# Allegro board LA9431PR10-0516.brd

Outline 284.1 x 113 mm; copper layers: TOP, GND1, IN1, GND2, IN2, IN3, VCC, IN4, GND3, BOTTOM. Coordinates in mm from the lower left corner of the outline.

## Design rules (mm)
net group _MSE: nets CLK_MSE DAT_MSE
net group BC_CLK_ECE1117: nets BC_CLK_ECE1117 BC_DAT_ECE1117
net group BC_CLK_ECE5048: nets BC_CLK_ECE5048 BC_DAT_ECE5048
net group CHARGER_SMBCLK: nets CHARGER_SMBCLK CHARGER_SMBDAT
net group CLK_DDC2_DOCK: nets CLK_DDC2_DOCK DAT_DDC2_DOCK
net group CLK_KBD: nets CLK_KBD DAT_KBD
net group CLK_PCIE_MINI2: nets CLK_PCIE_MINI2 CLK_PCIE_MINI2#
net group CLK_PCIE_MMI: nets CLK_PCIE_MMI CLK_PCIE_MMI#
net group CPU_DPB_AUX: nets CPU_DPB_AUX CPU_DPB_AUX#
net group CPU_DPB_CTRLCLK: nets CPU_DPB_CTRLCLK CPU_DPB_CTRLDAT
net group CPU_DPB_CTRLCLK_R: nets CPU_DPB_CTRLCLK_R CPU_DPB_CTRLDAT_R
net group CPU_DPC_AUX: nets CPU_DPC_AUX CPU_DPC_AUX#
net group CPU_DPC_CTRLCLK: nets CPU_DPC_CTRLCLK CPU_DPC_CTRLDAT
net group CS1: nets CSN1 CSP1
net group CSS_1: nets CSSN_1 CSSP_1
net group DAT_TP_SIO: nets CLK_TP_SIO DAT_TP_SIO
net group DDR_XDP_SMBCLK_R1: nets DDR_XDP_SMBCLK_R1 DDR_XDP_SMBDAT_R1
net group DIFFPAIR0: nets TMDSB_CON_CLK TMDSB_CON_CLK#
net group DOCK_DCIN_IS: nets DOCK_DCIN_IS+ DOCK_DCIN_IS-
net group DPB_DOCK_AUX: nets DPB_DOCK_AUX DPB_DOCK_AUX#
net group DPC_DOCK_AUX: nets DPC_DOCK_AUX DPC_DOCK_AUX#
net group I2C0_SCL: nets I2C0_SCL I2C0_SDA
net group LAN_SMBCLK: nets LAN_SMBCLK LAN_SMBDATA
net group LAN_SMBCLK_R: nets LAN_SMBCLK_R LAN_SMBDATA_R
net group MDP_AUX: nets MDP_AUX MDP_AUX#
net group MDP_AUX_C: nets MDP_AUX#_C MDP_AUX_C
net group MEM_SMBCLK: nets MEM_SMBCLK MEM_SMBDATA
net group NFC_SMBCLK: nets NFC_SMBCLK NFC_SMBDATA
net group PBAT_SMBCLK: nets PBAT_SMBCLK PBAT_SMBDAT
net group PS_USBP0_D: nets PS_USBP0_D+ PS_USBP0_D-
net group SB3: nets USB3TN2_C USB3TP2_C
net group SENSE: nets VCCSENSE VSSSENSE
net group SML0CLK: nets SML0CLK SML0DATA
net group SML1_SMBCLK: nets SML1_SMBCLK SML1_SMBDATA
net group SW_DPB_AUX: nets SW_DPB_AUX SW_DPB_AUX#
net group SW_DPB_AUX_C: nets SW_DPB_AUX#_C SW_DPB_AUX_C
net group SW_DPC_AUX: nets SW_DPC_AUX SW_DPC_AUX#
net group SW_DPC_AUX_C: nets SW_DPC_AUX#_C SW_DPC_AUX_C
net group TMDS_CLK_C: nets TMDS_CLK#_C TMDS_CLK_C
net group USB3RN2_D: nets USB3RN2_D- USB3RP2_D+
net group USB3RP1_D: nets USB3RN1_D- USB3RP1_D+
net group USB3RP3_D: nets USB3RN3_D- USB3RP3_D+
net group USB3TN1_D: nets USB3TN1_D- USB3TP1_D+
net group USB3TN3_D: nets USB3TN3_D- USB3TP3_D+
net group USB3TP2_D: nets USB3TN2_D- USB3TP2_D+
net group USBP1_R_D: nets USBP1_R_D+ USBP1_R_D-
net group USH_SMBCLK: nets USH_SMBCLK USH_SMBDAT
net group 15: nets USB3TN1 USB3TN1_RP_C USB3TP1 USB3TP1_RP_C
net group ASYNCHRONOUS: nets DDR3_DRAMRST# DDR3_DRAMRST#_CPU H_PROCHOT# H_PROCHOT#_R H_VCCST_PWRGD H_VCCST_PWRGD_XDP PROCHOT#_EC XDP_OBS0_R XDP_OBS1_R XDP_OBS2_R XDP_OBS3_R XDP_OBS4_R XDP_OBS5_R XDP_OBS6_R XDP_OBS7_R
net group CLK_SINGAL: nets CLK_PCI_5048 CLK_PCI_DOCK CLK_PCI_LPDEBUG CLK_PCI_MEC CLK_PCI_TPM_TCM PCI_CLK_LPC PCI_CLK_LPC_0 PCI_CLK_LPC_1
net group CONTROL LINK: nets PCH_CL_CLK1 PCH_CL_DATA1 PCH_CL_RST1#
net group CRT: nets BLUE_DOCK GREEN_DOCK HSYNC_DOCK RED_DOCK VSYNC_DOCK
net group DDR_A_CLK: nets M_CLK_DDR0 M_CLK_DDR1 M_CLK_DDR#0 M_CLK_DDR#1
net group DDR_A_CMD: nets DDR_A_BS0 DDR_A_BS1 DDR_A_BS2 DDR_A_CAS# DDR_A_MA0 DDR_A_MA1 DDR_A_MA2 DDR_A_MA3 DDR_A_MA4 DDR_A_MA5 DDR_A_MA6 DDR_A_MA7 DDR_A_MA8 DDR_A_MA9 DDR_A_MA10 DDR_A_MA11 DDR_A_MA12 DDR_A_MA13 DDR_A_MA14 DDR_A_MA15 DDR_A_RAS# DDR_A_WE#
net group DDR_A_CTL: nets DDR_CKE0_DIMMA DDR_CKE1_DIMMA DDR_CS0_DIMMA# DDR_CS1_DIMMA# M_ODT0 M_ODT1
net group DDR_A_D0: nets DDR_A_D0 DDR_A_D1 DDR_A_D2 DDR_A_D3 DDR_A_D4 DDR_A_D5 DDR_A_D6 DDR_A_D7
net group DDR_A_D1: nets DDR_A_D8 DDR_A_D9 DDR_A_D10 DDR_A_D11 DDR_A_D12 DDR_A_D13 DDR_A_D14 DDR_A_D15
net group DDR_A_D2: nets DDR_A_D16 DDR_A_D17 DDR_A_D18 DDR_A_D19 DDR_A_D20 DDR_A_D21 DDR_A_D22 DDR_A_D23
net group DDR_A_D3: nets DDR_A_D24 DDR_A_D25 DDR_A_D26 DDR_A_D27 DDR_A_D28 DDR_A_D29 DDR_A_D30 DDR_A_D31
net group DDR_A_D4: nets DDR_A_D32 DDR_A_D33 DDR_A_D34 DDR_A_D35 DDR_A_D36 DDR_A_D37 DDR_A_D38 DDR_A_D39
net group DDR_A_D5: nets DDR_A_D40 DDR_A_D41 DDR_A_D42 DDR_A_D43 DDR_A_D44 DDR_A_D45 DDR_A_D46 DDR_A_D47
net group DDR_A_D6: nets DDR_A_D48 DDR_A_D49 DDR_A_D50 DDR_A_D51 DDR_A_D52 DDR_A_D53 DDR_A_D54 DDR_A_D55
net group DDR_A_D7: nets DDR_A_D56 DDR_A_D57 DDR_A_D58 DDR_A_D59 DDR_A_D60 DDR_A_D61 DDR_A_D62 DDR_A_D63
net group DDR_A_DQS: nets DDR_A_DQS0 DDR_A_DQS1 DDR_A_DQS2 DDR_A_DQS3 DDR_A_DQS4 DDR_A_DQS5 DDR_A_DQS6 DDR_A_DQS7 DDR_A_DQS#0 DDR_A_DQS#1 DDR_A_DQS#2 DDR_A_DQS#3 DDR_A_DQS#4 DDR_A_DQS#5 DDR_A_DQS#6 DDR_A_DQS#7
net group DDR_B_CLK: nets M_CLK_DDR2 M_CLK_DDR3 M_CLK_DDR#2 M_CLK_DDR#3
net group DDR_B_CMD: nets DDR_B_BS0 DDR_B_BS1 DDR_B_BS2 DDR_B_CAS# DDR_B_MA0 DDR_B_MA1 DDR_B_MA2 DDR_B_MA3 DDR_B_MA4 DDR_B_MA5 DDR_B_MA6 DDR_B_MA7 DDR_B_MA8 DDR_B_MA9 DDR_B_MA10 DDR_B_MA11 DDR_B_MA12 DDR_B_MA13 DDR_B_MA14 DDR_B_MA15 DDR_B_RAS# DDR_B_WE#
net group DDR_B_CTL: nets DDR_CKE2_DIMMB DDR_CKE3_DIMMB DDR_CS2_DIMMB# DDR_CS3_DIMMB# M_ODT2 M_ODT3
net group DDR_B_D0: nets DDR_B_D0 DDR_B_D1 DDR_B_D2 DDR_B_D3 DDR_B_D4 DDR_B_D5 DDR_B_D6 DDR_B_D7
net group DDR_B_D1: nets DDR_B_D8 DDR_B_D9 DDR_B_D10 DDR_B_D11 DDR_B_D12 DDR_B_D13 DDR_B_D14 DDR_B_D15
net group DDR_B_D2: nets DDR_B_D16 DDR_B_D17 DDR_B_D18 DDR_B_D19 DDR_B_D20 DDR_B_D21 DDR_B_D22 DDR_B_D23
net group DDR_B_D3: nets DDR_B_D24 DDR_B_D25 DDR_B_D26 DDR_B_D27 DDR_B_D28 DDR_B_D29 DDR_B_D30 DDR_B_D31
net group DDR_B_D4: nets DDR_B_D32 DDR_B_D33 DDR_B_D34 DDR_B_D35 DDR_B_D36 DDR_B_D37 DDR_B_D38 DDR_B_D39
net group DDR_B_D5: nets DDR_B_D40 DDR_B_D41 DDR_B_D42 DDR_B_D43 DDR_B_D44 DDR_B_D45 DDR_B_D46 DDR_B_D47
net group DDR_B_D6: nets DDR_B_D48 DDR_B_D49 DDR_B_D50 DDR_B_D51 DDR_B_D52 DDR_B_D53 DDR_B_D54 DDR_B_D55
net group DDR_B_D7: nets DDR_B_D56 DDR_B_D57 DDR_B_D58 DDR_B_D59 DDR_B_D60 DDR_B_D61 DDR_B_D62 DDR_B_D63
net group DDR_B_DQS: nets DDR_B_DQS0 DDR_B_DQS1 DDR_B_DQS2 DDR_B_DQS3 DDR_B_DQS4 DDR_B_DQS5 DDR_B_DQS6 DDR_B_DQS7 DDR_B_DQS#0 DDR_B_DQS#1 DDR_B_DQS#2 DDR_B_DQS#3 DDR_B_DQS#4 DDR_B_DQS#5 DDR_B_DQS#6 DDR_B_DQS#7
net group DP: nets DPB_DOCK_LANE_N0 DPB_DOCK_LANE_N1 DPB_DOCK_LANE_N2 DPB_DOCK_LANE_N3 DPB_DOCK_LANE_P0 DPB_DOCK_LANE_P1 DPB_DOCK_LANE_P2 DPB_DOCK_LANE_P3 DPB_LANE_N0 DPB_LANE_N0_C DPB_LANE_N1 DPB_LANE_N1_C DPB_LANE_N2 DPB_LANE_N2_C DPB_LANE_N3 DPB_LANE_N3_C DPB_LANE_P0 DPB_LANE_P0_C DPB_LANE_P1 DPB_LANE_P1_C DPB_LANE_P2 DPB_LANE_P2_C DPB_LANE_P3 DPB_LANE_P3_C DPC_DOCK_LANE_N0 DPC_DOCK_LANE_N1 DPC_DOCK_LANE_N2 DPC_DOCK_LANE_N3 DPC_DOCK_LANE_P0 DPC_DOCK_LANE_P1 DPC_DOCK_LANE_P2 DPC_DOCK_LANE_P3 DPC_LANE_N0 DPC_LANE_N0_C DPC_LANE_N1 DPC_LANE_N1_C DPC_LANE_N2 DPC_LANE_N2_C DPC_LANE_N3 DPC_LANE_N3_C DPC_LANE_P0 DPC_LANE_P0_C DPC_LANE_P1 DPC_LANE_P1_C DPC_LANE_P2 DPC_LANE_P2_C DPC_LANE_P3 DPC_LANE_P3_C MDP_LANE_N0 MDP_LANE_N0_C MDP_LANE_N1 MDP_LANE_N1_C MDP_LANE_N2 MDP_LANE_N2_C MDP_LANE_N3 MDP_LANE_N3_C MDP_LANE_P0 MDP_LANE_P0_C MDP_LANE_P1 MDP_LANE_P1_C MDP_LANE_P2 MDP_LANE_P2_C MDP_LANE_P3 MDP_LANE_P3_C
net group DP12412_AUX_C: nets DP12412_AUX#_C
net group DP_AUX: nets VMM2310_AUXN VMM2310_AUXP VMM2310_HDP VMM2310_SCL VMM2310_SDA VMM2310_TX2N0 VMM2310_TX2N1 VMM2310_TX2N2 VMM2310_TX2N3 VMM2310_TX2P0
net group DP_DDC: nets VMM_DPB_CTRLCLK VMM_DPB_CTRLDAT VMM_DPC_CTRLCLK VMM_DPC_CTRLDAT
net group DP_MAIN: nets DDI2_LANE_N0 DDI2_LANE_N1 DDI2_LANE_N2 DDI2_LANE_N3 DDI2_LANE_P0 DDI2_LANE_P1 DDI2_LANE_P2 DDI2_LANE_P3 DP12412_AUX DP12412_AUX# DP12412_AUX_C DP12412_N0 DP12412_N0_C DP12412_N1 DP12412_N1_C DP12412_N2 DP12412_N2_C DP12412_N3 DP12412_N3_C DP12412_P0 DP12412_P0_C DP12412_P1 DP12412_P1_C DP12412_P2 DP12412_P2_C DP12412_P3 DP12412_P3_C
net group EDP: nets EDP_CPU_AUX EDP_CPU_AUX# EDP_CPU_AUX#_C EDP_CPU_AUX_C EDP_CPU_LANE_N0 EDP_CPU_LANE_N0_C EDP_CPU_LANE_N1 EDP_CPU_LANE_N1_C EDP_CPU_LANE_P0 EDP_CPU_LANE_P0_C EDP_CPU_LANE_P1 EDP_CPU_LANE_P1_C
net group HDA: nets PCH_AZ_BITCLK PCH_AZ_CODEC_BITCLK PCH_AZ_CODEC_RST# PCH_AZ_CODEC_SDIN0 PCH_AZ_CODEC_SDOUT PCH_AZ_CODEC_SYNC PCH_AZ_RST# PCH_AZ_SDIN0_R PCH_AZ_SDOUT PCH_AZ_SYNC
net group HDMI: nets DDI1_LANE_N0 DDI1_LANE_N1 DDI1_LANE_N2 DDI1_LANE_N3 DDI1_LANE_P0 DDI1_LANE_P1 DDI1_LANE_P2 DDI1_LANE_P3 TMDS_N0_C TMDS_N1_C TMDS_N2_C TMDS_P0_C TMDS_P1_C TMDS_P2_C TMDSB_CON_N0 TMDSB_CON_N1 TMDSB_CON_N2 TMDSB_CON_P0 TMDSB_CON_P1 TMDSB_CON_P2
net group HP: nets AUD_HP_OUT_L AUD_HP_OUT_R AUD_OUT_L AUD_OUT_R
net group LAN: nets DOCK_LOM_TRD0+ DOCK_LOM_TRD0- DOCK_LOM_TRD1+ DOCK_LOM_TRD1- DOCK_LOM_TRD2+ DOCK_LOM_TRD2- DOCK_LOM_TRD3+ DOCK_LOM_TRD3- LAN_TX0+ LAN_TX0+R LAN_TX0- LAN_TX0-R LAN_TX1+ LAN_TX1+R LAN_TX1- LAN_TX1-R LAN_TX2+ LAN_TX2+R LAN_TX2- LAN_TX2-R LAN_TX3+ LAN_TX3+R LAN_TX3- LAN_TX3-R NB_LAN_TX0+ NB_LAN_TX0- NB_LAN_TX1+ NB_LAN_TX1- NB_LAN_TX2+ NB_LAN_TX2- NB_LAN_TX3+ NB_LAN_TX3- SW_LAN_TX0+ SW_LAN_TX0- SW_LAN_TX1+ SW_LAN_TX1- SW_LAN_TX2+ SW_LAN_TX2- SW_LAN_TX3+ SW_LAN_TX3-
net group LOW: nets CFD_PWRBTN#_XDP DSWODVREN H_THERMTRIP# H_THERMTRIP#_R INTRUDER# PCH_DPWROK PCH_INTVRMEN PCH_PCIE_WAKE# PCH_RSMRST#_Q PCH_RSMRST#_R PCH_RTCRST# PM_APWROK SIO_PWRBTN# SIO_RCIN# SRTCRST# SYS_PWROK SYS_PWROK_R SYS_PWROK_XDP SYS_RESET#
net group LPC: nets LPC_LAD0 LPC_LAD1 LPC_LAD2 LPC_LAD3 LPC_LFRAME#
net group MPD: nets SW_MDP_AUX#_C
net group PCIE: nets PCIE_PRX_GLANTX_N3 PCIE_PRX_GLANTX_N3_C PCIE_PRX_GLANTX_P3 PCIE_PRX_GLANTX_P3_C PCIE_PRX_MMITX_N5 PCIE_PRX_MMITX_N5_C PCIE_PRX_MMITX_P5 PCIE_PRX_MMITX_P5_C PCIE_PRX_WLANTX_N4 PCIE_PRX_WLANTX_P4 PCIE_PTX_GLANRX_N3 PCIE_PTX_GLANRX_N3_C PCIE_PTX_GLANRX_P3 PCIE_PTX_GLANRX_P3_C PCIE_PTX_MMIRX_N5 PCIE_PTX_MMIRX_N5_C PCIE_PTX_MMIRX_P5 PCIE_PTX_MMIRX_P5_C PCIE_PTX_WLANRX_N4 PCIE_PTX_WLANRX_N4_C PCIE_PTX_WLANRX_P4 PCIE_PTX_WLANRX_P4_C
net group PLAT_CLK: nets CLK_PCIE_LAN CLK_PCIE_LAN# CLK_PCIE_MINI1 CLK_PCIE_MINI1#
net group POWER: nets +LCDVDD +VCCIO_OUT +VCCIOA_OUT
net group REM: nets REM_DIODE1_N REM_DIODE1_P REM_DIODE2_N REM_DIODE2_P REM_DIODE4_N REM_DIODE4_P
net group RTC: nets PCH_RTCX1 PCH_RTCX1_R PCH_RTCX2
net group SATA: nets SATA_PRX_DKTX_N0 SATA_PRX_DKTX_N0_C SATA_PRX_DKTX_P0 SATA_PRX_DKTX_P0_C SATA_PRX_DTX_N1 SATA_PRX_DTX_N1_C SATA_PRX_DTX_P1 SATA_PRX_DTX_P1_C SATA_PRX_MSATATX_N3 SATA_PRX_MSATATX_P3 SATA_PTX_DKRX_N0 SATA_PTX_DKRX_N0_C SATA_PTX_DKRX_P0 SATA_PTX_DKRX_P0_C SATA_PTX_DRX_N1 SATA_PTX_DRX_N1_C SATA_PTX_DRX_P1 SATA_PTX_DRX_P1_C SATA_PTX_MSATARX_N3 SATA_PTX_MSATARX_N3_C SATA_PTX_MSATARX_P3 SATA_PTX_MSATARX_P3_C
net group SD: nets SD/MMCCD# SD/MMCCLK SD/MMCCLK_R SD/MMCCMD SD/MMCDAT0 SD/MMCDAT0_D SD/MMCDAT1 SD/MMCDAT1_D SD/MMCDAT2 SD/MMCDAT2_R SD/MMCDAT3 SD/MMCDAT3_R SD_UHS2_D0N SD_UHS2_D0N_D SD_UHS2_D0P SD_UHS2_D0P_D SD_UHS2_D1N SD_UHS2_D1N_D SD_UHS2_D1P SD_UHS2_D1P_D SDWP
net group SIM: nets UIM_CLK UIM_DATA UIM_RESET UIM_VPP
net group SMB: nets BAY_SMBCLK BAY_SMBDAT BC_INT#_ECE1117 BC_INT#_ECE5048 CARD_SMBCLK CARD_SMBDAT DDR_XDP_WAN_SMBCLK DDR_XDP_WAN_SMBDAT DOCK_SMB_CLK DOCK_SMB_DAT GPU_SMBCLK GPU_SMBDAT LCD_SMBCLK LCD_SMBDAT WWAN_SMBCLK WWAN_SMBDAT
net group SPI: nets PCH_SPI_CLK PCH_SPI_CS0# PCH_SPI_CS1# PCH_SPI_DIN PCH_SPI_DO PCH_SPI_DO2 PCH_SPI_DO3 SPI_CLK32 SPI_CLK64 SPI_DIN32 SPI_DIN64 SPI_DO32 SPI_DO64 SPI_PCH_CS0#_R SPI_PCH_CS1#_R SPI_PCH_DO2_32 SPI_PCH_DO2_64 SPI_PCH_DO3_32 SPI_PCH_DO3_64
net group SPK: nets INT_SPK_L+ INT_SPK_L- INT_SPK_R+ INT_SPK_R- INT_SPKR_L- INT_SPKR_R+ INT_SPKR_R-
net group SVID: nets H_CPU_SVIDALRT# VIDALERT_N VIDSCLK VIDSOUT
net group SW_MDP_AUX_C: nets SW_MDP_AUX_C
net group THERMAL: nets PECI_EC PECI_EC_R THERMATRIP2#
net group USB2: nets DOCK_USBP0+ DOCK_USBP0- DOCK_USBP0_D+ DOCK_USBP0_D- DOCK_USBP5+ DOCK_USBP5- SW_USBP0+ SW_USBP0- SW_USBP5+ SW_USBP5- USBP0+ USBP0- USBP0_D+ USBP0_D- USBP1+ USBP1- USBP2+ USBP2- USBP3+ USBP3- USBP3_D+ USBP3_D- USBP4+ USBP4- USBP5+ USBP5- USBP5_D+ USBP5_D- USBP6+ USBP6- USBP7+ USBP7-
net group USB3: nets DOCK_USB3RN3 DOCK_USB3RP3 DOCK_USB3TN3 DOCK_USB3TP3 SW_USB3RN3 SW_USB3RP3 SW_USB3TN3 SW_USB3TN3_C SW_USB3TP3 SW_USB3TP3_C USB3RN1 USB3RN2 USB3RN3 USB3RP1 USB3RP2 USB3RP3 USB3TN2 USB3TN3 USB3TP2 USB3TP3
nets with their own width: min track width 0.203; nets CLK_27M_IN CLK_27M_IN_R CLK_27M_OUT MEC_XTAL1 MEC_XTAL2 XTAL24_IN XTAL24_IN_R XTAL24_OUT XTALI XTALO XTALO_R
nets with their own width: min track width 0.254; nets N21375241 NB_PSID RING2_L
nets with their own width: min track width 0.305; nets SM_RCOMP0 SM_RCOMP1 SM_RCOMP2
nets with their own width: min track width 0.356; nets +0.675V_DDR_VTT
nets with their own width: min track width 0.381; nets AUD_HP_OUT_L1
nets with their own width: min track width 0.508; nets +0.675V_P +1.05V_M +1.05V_M_JTAG +1.05V_MP +1.05V_RUN +1.5V_THERMAL +1.05V_VCCST +1.35V_MEN_P +3.3V_ALW +3.3V_ALW2 +3.3V_ALWP +3.3V_CAM_Q +3.3V_HDD +3.3V_MSATA_WWAN +3.3V_RTC_LDO +3.3V_RUN +3.3V_RUN_AUDIO +3.3V_RUN_VDDA +3.3V_RUN_VMM +3.3V_VTR +5V_ALW +5V_ALW2 +5V_ALWP +5V_HDMI_DDC +5V_RUN +ALC290_LDO_CAP +ALC3226_CPVEE +ALC3226_VREF +AUX_LDO +BATT_SUM +CAP_LDO +CHGR_DC_IN +COINCELL +DC1_PWR_SRC +DC_IN +DC_IN_SS +DCIN +DCPRRTC +DIMM1_VREF_DQ +DIMM2_VREF_DQ +DOCK_PWR_BAR +DVDD_CORE +LOM_VCT +NBDOCK_DC_IN_SS +PBATT +PBATT_IN_SS +PCH_ASATA3PLL +PCH_AUSB3PLL +PCH_DCPSUS +PCH_DCPSUS1 +PCH_DCPSUS4 +PCH_RTC_VCCSUS3_3 +PCH_VCC1P05 +PCH_VCCACLKPLL +PCH_VCCDSW +PCH_VCCDSW_R +PECI_VREF +PWR_SRC +PWR_SRC_AC +RSVD_VCC3P3_1 +RTC_CELL +RTC_CELL_VBAT +SD_IO_LDO +SDC_IN +SIM_PWR +SM_VREF_CA +SM_VREF_CA_DIMM +SM_VREF_DQ0 +SM_VREF_DQ0_DIMM1 +SM_VREF_DQ1 +SM_VREF_DQ1_DIMM2 +V1.05S_APLLOPI +V1.05SP_B+ +V_DDR_REF +VCC_CORE +VCC_PWR_SRC +VCHGR +VDDA_AVDD1 +VDDA_AVDD2 +VLDOIN_1.35V +VR_CAP +VREFOUT EDP_COMP GND GNDA
nets with their own width: min track width 1.016; nets +0.9V_LAN +1.2V_LDO +1.2V_LDO_AIN +1.05V_VMM_VDD +1.8V_RUN_CARD +3.3V_ALW_PCH +3.3V_ALW_U37 +3.3V_ALW_U38 +3.3V_CAM +3.3V_LAN +3.3V_LAN_OUT +3.3V_M +3.3V_RUN_AIN +3.3V_RUN_CARD +3.3V_RUN_TPM +3.3V_RUN_VDDIO +3.3V_TP +3.3V_TSP +3.3V_TSP_Q +BL_PWR_SRC +GND_CHASSIS +PCH_VCCDSW3_3 +VDDA_PVDD +VDISPLAY_VCC +VHDMI_VCC REGCTL_PNP10
nets with their own width: min track width 1.524; nets +1.05V_VMM_VDDTX +3.3V_SUS +3.3V_WLAN +USB_SIDE_PWR
nets with their own width: min track width 2.032; nets +1.05V_MODPHY +1.05V_MODPHY_PCH +1.05V_RUN_VMM +5V_RUN_AUDIO +USB_PWR
nets with their own width: min track width 2.54; nets +5V_USB_CHG_PWR

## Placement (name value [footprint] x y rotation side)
C1  -  [C_0402]  248.34 8.6 90 top
C3  -  [C_0402]  94.3 97.38 180 bottom
C5  -  [C_0402]  177.52 83.86 0 bottom
C6  -  [C_0402]  175.43 65.44 0 bottom
C7  -  [C_0805]  50.85 45.15 270 top
C8  -  [C_0603]  197.16 77.95 270 bottom
C9  -  [C_0402]  192.19 83.16 0 bottom
C10  -  [C_0402]  196.99 80.63 270 bottom
C11  -  [C_0402]  196.96 84.06 270 bottom
C12  -  [C_0402]  199.52 81.25 0 bottom
C13  -  [C_0402]  198.27 81.18 90 bottom
C14  -  [C_0402]  197.76 84.96 180 bottom
C15  -  [C_0402]  199.59 80.39 270 bottom
C16  -  [C_0603]  197.73 86.08 180 bottom
C17  -  [C_0402]  195.33 78.59 180 bottom
C18  -  [C_0402]  195.29 77.34 180 bottom
C19  -  [C_0402]  187.16 79.76 0 top
C20  -  [C_0402]  187.16 78.88 0 top
C21  -  [C_0603]  203.81 75.93 0 bottom
C22  -  [C_0402]  195.05 84.75 0 bottom
C23  -  [C_0402]  199.57 82.26 90 bottom
C24  -  [C_0402]  192.33 81.53 270 bottom
C25  -  [C_0603]  192.91 75.09 90 bottom
C26  -  [C_0603]  189.43 89.06 90 top
C27  -  [C_0402]  198.35 78.61 0 bottom
C28  -  [C_0402]  193.27 84.75 0 bottom
C29  -  [C_0402]  198.79 84.68 0 bottom
C34  -  [C_0402]  191.87 77.44 0 bottom
C42  -  [C_0402]  188.07 77.11 90 top
C43  -  [C_0402]  187.95 76.12 270 top
C50  -  [C_0402]  270.04 6.32 0 top
C52  -  [C_0603]  65.52 70.21 180 bottom
C54  -  [C_0402]  60.13 67.89 110 bottom
C55  -  [C_0402]  59.24 67.57 110 bottom
C56  -  [C_0402]  57.25 67.81 110 bottom
C57  -  [C_0402]  57.2 65.19 110 bottom
C59  -  [C_0402]  58.09 68.12 110 bottom
C60  -  [C_0402]  58.03 65.5 110 bottom
C61  -  [C_0402]  146.67 103.78 90 top
C62  -  [C_0402]  140.58 102.7 90 top
C63  -  [C_0402]  59.49 70.83 90 bottom
C64  -  [C_0402]  53.21 67.22 0 top
C65  -  [C_0603]  65.52 71.92 180 bottom
C66  -  [C_0402]  70.61 66.9 180 top
C67  -  [C_0402]  87.99 94.63 180 top
C68  -  [C_0402]  67.22 77.06 0 top
C76  -  [C_0402]  178.88 81 180 bottom
C85  -  [C_0402]  178.3 75.55 270 bottom
C87  -  [C_0402]  199.24 99.85 180 bottom
C88  -  [C_0603]  187.38 98.93 270 bottom
C93  -  [C_0402]  210.55 83.36 270 bottom
C94  -  [C_0402]  201.47 83.17 270 bottom
C95  -  [C_0402]  200.52 83.17 270 bottom
C97  -  [C_0402]  180.33 82.57 90 bottom
C98  -  [C_0402]  185.37 89.9 0 bottom
C99  -  [C_0402]  185.37 88.95 0 bottom
C103  -  [C_0402]  193.85 94.86 270 bottom
C105  -  [C_0402]  45.4 15.85 180 top
C106  -  [C_0402]  45.4 16.74 180 top
C108  -  [C_0402]  45.4 20.09 180 top
C109  -  [C_0402]  45.4 19.2 180 top
C113  -  [C_0402]  50.27 13.21 0 bottom
C114  -  [C_0402]  50.27 12.25 0 bottom
C115  -  [C_0402]  275.72 42.77 180 top
C116  -  [C_0603]  268.31 40.17 90 top
C117  -  [C_0603]  275.2 43.98 180 top
C118  -  [C_0603]  264.91 31.34 90 top
C119  -  [C_0402]  271.41 28.51 270 top
C120  -  [C_0402]  275.04 28.52 270 top
C121  -  [C_0603]  269.44 28.88 270 top
C122  -  [C_0603]  267.67 34.96 180 top
C123  -  [C_0402]  267.2 33.15 180 top
C124  -  [C_0402]  280.39 21.75 180 top
C125  -  [C_0402]  277.66 21.75 0 top
C126  -  [C_0402]  275.91 21.88 180 top
C127  -  [C_0402]  272.9 21.88 0 top
C128  -  [C_0603]  267.55 37.19 180 top
C129  -  [C_0402]  267.61 36.04 180 top
C130  -  [C_0402]  270.52 26.8 270 top
C131  -  [C_0603]  271.77 42.39 0 bottom
C132  -  [C_0603]  200.42 76.97 270 bottom
C134  -  [C_0603]  269.58 39.47 0 top
C135  -  [C_0402]  272.55 26.75 270 top
C136  -  [C_0402]  273.42 26.73 270 top
C137  -  [C_0402]  278 23.41 180 top
C138  -  [C_0603]  270.85 40.74 180 top
C139  -  [C_0402]  269.8 16.42 0 top
C140  -  [C_0603]  275.72 42.76 90 bottom
C141  -  [C_0402]  270.36 66.37 90 top
C142  -  [C_0402]  269.42 66.38 90 top
C144  -  [C_0402]  267.14 42.27 180 top
C145  -  [C_0402]  275.2 24.19 0 top
C146  -  [C_0402]  275.2 25.09 0 top
C147  -  [C_0402]  270.31 19.23 0 top
C148  -  [C_0402]  270.31 18.34 0 top
C150  -  [C_0402]  267.93 39.23 270 top
C151  -  [C_0603]  164.07 83.6 270 top
C152  -  [C_0402]  166.17 83.3 270 top
C153  -  [C_0402]  165.21 83.3 270 top
C154  -  [C_0402]  165.93 89.51 180 top
C155  -  [C_0402]  187.17 80.68 0 top
C156  -  [C_0402]  187.17 81.57 0 top
C157  -  [C_0402]  187.17 82.46 0 top
C158  -  [C_0402]  187.17 83.35 0 top
C159  -  [C_0402]  187.19 84.24 0 top
C160  -  [C_0402]  187.19 85.13 0 top
C161  -  [C_0402]  187.17 86.02 0 top
C162  -  [C_0402]  187.17 86.91 0 top
C163  -  [C_0402]  178.54 87.99 0 top
C164  -  [C_0402]  178.54 87.1 0 top
C165  -  [C_0402]  178.16 86.14 0 top
C166  -  [C_0402]  178.16 85.25 0 top
C167  -  [C_0402]  274.17 43.89 270 bottom
C168  -  [C_0402]  178.52 83.38 270 top
C169  -  [C_0603]  273.22 43.64 180 bottom
C170  -  [C_0402]  177.63 83.38 270 top
C171  -  [C_0402]  271.68 87.74 180 top
C172  -  [C_0402]  176.71 82.6 270 top
C173  -  [C_0402]  175.82 82.6 270 top
C174  -  [C_0402]  227.52 89.16 180 top
C175  -  [C_0402]  227.52 87.21 180 top
C176  -  [C_0402]  250.54 71.97 270 top
C177  -  [C_0402]  253.8 82.51 90 top
C178  -  [C_0402]  252.39 71.05 90 top
C179  -  [C_0402]  249.66 71.97 270 top
C180  -  [C_0603]  256.91 70.71 90 top
C181  -  [C_0402]  253.28 71.05 90 top
C182  -  [C_0603]  258.5 81.76 90 top
C183  -  [C_0402]  251.13 82.45 90 top
C184  -  [C_0402]  255.83 71.28 90 top
C185  -  [C_0402]  251.45 71.93 270 top
C186  -  [C_0402]  248.72 71.93 270 top
C187  -  [C_0805]  258.43 70.75 90 top
C188  -  [C_0402]  268.83 21.13 180 top
C189  -  [C_0402]  259.19 78.03 270 top
C190  -  [C_0402]  259.19 78.89 90 top
C191  -  [C_0402]  194.81 94.86 270 bottom
C192  -  [C_0402]  230.51 97.05 270 top
C193  -  [C_0402]  230.35 99.42 0 bottom
C194  -  [C_0402]  228.7 97.21 180 top
C198  -  [C_0402]  243.03 81.94 0 top
C199  -  [C_0402]  196.33 94.69 270 bottom
C200  -  [C_0402]  40.56 38.32 90 top
C201  -  [C_0402]  41.96 28.69 270 top
C202  -  [C_0402]  41.01 28.69 270 top
C203  -  [C_0402]  37.77 28.69 270 top
C204  -  [C_0402]  38.72 28.69 270 top
C206  -  [C_0402]  186.84 8.09 90 top
C207  -  [C_0402]  187.76 8.09 90 top
C208  -  [C_0402]  188.65 8.09 90 top
C209  -  [C_0402]  197.28 94.69 270 bottom
C210  -  [C_0402]  263.37 19.85 0 top
C211  -  [C_0603]  252.27 26.07 180 top
C212  -  [C_0402]  255.45 25.68 90 top
C213  -  [C_0603]  253.8 12.04 180 top
C214  -  [C_0402]  257.29 25.68 90 top
C215  -  [C_0402]  255.38 14.78 270 top
C216  -  [C_0402]  253.61 14.73 90 top
C217  -  [C_0402]  264.52 18.96 180 top
C218  -  [C_0402]  256.4 26.59 270 top
C219  -  [C_0402]  250.93 17.94 0 top
C220  -  [C_0603]  252.53 13.37 90 top
C221  -  [C_0603]  253.48 26.71 270 top
C222  -  [C_0402]  254.56 26.59 270 top
C223  -  [C_0603]  265.07 17.88 180 top
C224  -  [C_0603]  250.88 24.8 0 top
C225  -  [C_0603]  250.88 23.53 0 top
C226  -  [C_0402]  251.82 22.45 0 top
C227  -  [C_0402]  249.24 20.28 180 top
C228  -  [C_0603]  251.55 15.99 180 top
C229  -  [C_0402]  251.63 17.07 180 top
C230  -  [C_0603]  264.91 26.01 180 top
C231  -  [C_0402]  262.62 25.74 180 top
C232  -  [C_0402]  256.27 13.87 90 top
C233  -  [C_0402]  258.12 13.87 90 top
C234  -  [C_0402]  260.85 14.06 90 top
C235  -  [C_0402]  261.43 28.04 180 top
C236  -  [C_0402]  261.43 27.15 180 top
C237  -  [C_0402]  263.53 28.68 180 top
C238  -  [C_0402]  263.53 29.57 180 top
C239  -  [C_0402]  249.24 18.06 180 top
C240  -  [C_0603]  249.73 19.14 180 top
C241  -  [C_0402]  210.26 14.92 180 top
C242  -  [C_0402]  207.7 22.67 0 bottom
C243  -  [C_0402]  207.7 23.56 0 bottom
C244  -  [C_0402]  205.54 59.41 270 top
C245  -  [C_0402]  204.65 59.41 270 top
C246  -  [C_0402]  274.69 5.12 180 top
C247  -  [C_0603]  274.78 6.2 180 top
C248  -  [C_0402]  206.81 61.96 270 top
C249  -  [C_0402]  207.44 66.45 90 top
C250  -  [C_0402]  205.91 43.93 90 top
C251  -  [C_0805]  206.08 64.32 90 top
C252  -  [C_0402]  206.62 53.45 270 top
C253  -  [C_B2]  204.1 61.67 270 bottom
C254  -  [C_B2]  204.04 58.84 90 bottom
C255  -  [C_0402]  264.29 21.69 180 top
C256  -  [C_0402]  249.21 15.82 180 top
C257  -  [C_0402]  207.2 26.62 270 bottom
C258  -  [C_0402]  208.1 26.62 270 bottom
C259  -  [C_0402]  210.86 9.28 90 top
C260  -  [C_0402]  209 25.7 90 bottom
C261  -  [C_0402]  210.76 21.73 270 top
C262  -  [C_0603]  209.58 20.83 90 top
C269  -  [C_0402]  191.5 94.86 270 bottom
C270  -  [C_0402]  192.39 94.86 270 bottom
C271  -  [C_0402]  189.22 94.86 270 bottom
C272  -  [C_0402]  190.17 94.86 270 bottom
C273  -  [C_0402]  193.6 99.15 90 bottom
C274  -  [C_0402]  195 99.15 90 bottom
C275  -  [C_0402]  196.08 99.15 90 bottom
C276  -  [C_0402]  197.35 99.15 90 bottom
C277  -  [C_0402]  191.19 99.15 90 bottom
C278  -  [C_0402]  192.58 99.15 90 bottom
C279  -  [C_0402]  188.9 99.15 90 bottom
C280  -  [C_B2]  226.01 90.78 180 bottom
C281  -  [C_0402]  219.65 94.72 180 top
C282  -  [C_0402]  203.3 93.33 180 top
C283  -  [C_0402]  203.3 92.44 180 top
C284  -  [C_0603]  231.99 87.25 0 bottom
C285  -  [C_0402]  232.32 85.95 0 bottom
C287  -  [C_0402]  71.49 85.46 270 top
C288  -  [C_0603]  103.49 103.06 270 top
C289  -  [C_0402]  103.05 104.23 90 top
C290  -  [C_B2]  83.01 96.35 0 bottom
C291  -  [C_0402]  76.11 96.3 0 top
C292  -  [C_0402]  78.09 87.43 270 top
C293  -  [C_0402]  79.05 87.43 270 top
C294  -  [C_0402]  114.21 93.34 90 top
C295  -  [C_0402]  115.1 94.26 270 bottom
C296  -  [C_0402]  115.1 93.34 90 top
C297  -  [C_0402]  115.99 94.26 270 bottom
C298  -  [C_0402]  115.99 93.34 90 top
C299  -  [C_0402]  116.88 94.26 270 bottom
C300  -  [C_0402]  119.54 94.26 270 bottom
C301  -  [C_0402]  120.43 94.26 270 bottom
C302  -  [C_0402]  114.21 94.26 270 bottom
C303  -  [C_0402]  116.88 93.34 90 top
C304  -  [C_0402]  117.77 94.26 270 bottom
C305  -  [C_0402]  117.77 93.34 90 top
C306  -  [C_0402]  118.66 94.26 270 bottom
C307  -  [C_0402]  118.66 93.34 90 top
C308  -  [C_0402]  119.54 93.34 90 top
C309  -  [C_0402]  120.43 93.34 90 top
C310  -  [C_0402]  122.72 96.92 270 bottom
C311  -  [C_0402]  123.38 109 180 top
C312  -  [C_0402]  128.7 104.99 90 top
C313  -  [C_0402]  129.65 104.99 90 top
C314  -  [C_0402]  138.15 97.51 0 top
C315  -  [C_0402]  138.15 98.4 0 top
C316  -  [C_0402]  144.26 109.02 270 top
C317  -  [C_0603]  111.8 96.8 270 bottom
C318  -  [C_0603]  108.26 93.07 0 bottom
C319  -  [C_0402]  147.43 96.35 90 bottom
C320  -  [C_0402]  244.08 96.84 270 top
C321  -  [C_0402]  243.19 96.84 270 top
C322  -  [C_0402]  79.67 83.03 0 top
C323  -  [C_0603]  259.64 81.95 270 bottom
C324  -  [C_0603]  258.37 81.95 270 bottom
C325  -  [C_0603]  247.7 81.83 270 bottom
C326  -  [C_0603]  246.37 81.83 270 bottom
C327  -  [C_1808]  267.21 86.11 180 bottom
C328  -  [C_0603]  16 42.52 180 top
C329  -  [C_0402]  19.74 41.74 90 bottom
C330  -  [C_0402]  13.36 32.92 180 top
C331  -  [C_0402]  12.76 35.22 180 top
C332  -  [C_0402]  28.55 30.07 0 top
C333  -  [C_0402]  184.98 100.75 180 bottom
C334  -  [C_0402]  18.34 41.74 90 bottom
C336  -  [C_0603]  18.86 40.22 0 bottom
C337  -  [C_0402]  12.89 39.33 90 top
C338  -  [C_0402]  194.6 41.76 0 top
C339  -  [C_0402]  30.71 36.3 0 top
C340  -  [C_0402]  11.81 6.26 180 top
C341  -  [C_0402]  256.41 29.57 180 top
C342  -  [C_0402]  12.64 3.47 180 top
C343  -  [C_0402]  12.64 7.21 180 top
C344  -  [C_0402]  14.48 4.36 180 top
C345  -  [C_0402]  14.54 14.26 180 top
C346  -  [C_0402]  32.88 13.32 270 top
C347  -  [C_0402]  17.34 14.44 180 top
C348  -  [C_0603]  16.07 5.63 90 top
C349  -  [C_0402]  19.1 7.29 270 top
C350  -  [C_0402]  31.98 15.98 0 top
C351  -  [C_0402]  25.9 7.29 270 top
C352  -  [C_0402]  31.99 13.32 270 top
C353  -  [C_0402]  17.34 13.55 180 top
C354  -  [C_0402]  29.58 22.25 90 top
C355  -  [C_0402]  17.34 17.18 180 top
C356  -  [C_0402]  24.18 22.25 90 top
C357  -  [C_0402]  35.24 11.53 180 top
C358  -  [C_0402]  28.13 7.28 180 top
C359  -  [C_0402]  29.29 6.27 180 top
C360  -  [C_0402]  19.37 22.2 180 top
C361  -  [C_0402]  29.82 7.28 0 top
C362  -  [C_0402]  12 16.55 180 top
C363  -  [C_0402]  34.26 16.85 0 top
C364  -  [C_0402]  15.55 12.09 90 top
C365  -  [C_0402]  15.55 11.16 270 top
C366  -  [C_0603]  27.23 4.93 0 top
C367  -  [C_0402]  31.98 9.69 0 top
C368  -  [C_0402]  24.99 4.8 0 top
C369  -  [C_0402]  24.94 7.29 270 top
C370  -  [C_0402]  128.7 72.38 270 top
C371  -  [C_0402]  31.98 19.04 0 top
C372  -  [C_0402]  126.5 17.47 180 top
C373  -  [C_0402]  93.27 57.01 270 bottom
C374  -  [C_0402]  199.44 8.34 90 top
C375  -  [C_0402]  202.3 8.34 90 top
C376  -  [C_0402]  203.19 8.34 90 top
C377  -  [C_0402]  192.7 16.49 0 top
C378  -  [C_0402]  190.06 16.31 0 top
C379  -  [C_0402]  192.66 14.02 180 top
C380  -  [C_0402]  189.78 13.99 0 top
C382  -  [C_0402]  190.23 99.15 90 bottom
C383  -  [C_0402]  269.37 82.35 0 top
C384  -  [C_0402]  36.82 38.38 90 top
C385  -  [C_0603]  270.84 41.99 180 top
C386  -  [C_0402]  41.33 9.64 270 top
C387  -  [C_0402]  38.04 18.64 180 top
C388  -  [C_0402]  249.89 14.4 180 top
C389  -  [C_0402]  204.72 72.36 270 bottom
C390  -  [C_0402]  208.48 70.51 270 bottom
C391  -  [C_0402]  209.37 70.51 270 bottom
C392  -  [C_0402]  194.17 72.36 90 bottom
C393  -  [C_0402]  212.71 71.11 0 bottom
C394  -  [C_0402]  196.66 73.84 0 top
C396  -  [C_0402]  189.76 31.29 180 top
C397  -  [C_0402]  189.75 32.44 180 top
C398  -  [C_0402]  189.75 33.45 180 top
C399  -  [C_0402]  188.77 35.27 180 top
C400  -  [C_0402]  185.75 68.1 180 top
C401  -  [C_0402]  186.49 68.57 270 bottom
C402  -  [C_0402]  188.9 68.57 270 bottom
C403  -  [C_0402]  189.51 71.21 0 top
C404  -  [C_0402]  10 37.86 90 top
C405  -  [C_0603]  262.62 31.34 90 top
C406  -  [C_0402]  246.32 73.82 180 top
C407  -  [C_0402]  203.94 39 90 top
C408  -  [C_0603]  272.97 47.73 180 bottom
C409  -  [C_0402]  203.91 28.63 90 top
C410  -  [C_0603]  267.81 30.77 180 top
C411  -  [C_0402]  235.27 91.26 180 top
C412  -  [C_0402]  157.73 91.08 270 top
C413  -  [C_0603]  147.92 90.35 0 top
C414  -  [C_0402]  157.42 111.48 180 top
C415  -  [C_0402]  155.64 111.48 180 top
C416  -  [C_0402]  167.51 99.35 180 top
C417  -  [C_0402]  159.59 105.68 90 top
C418  -  [C_0402]  167.83 98.46 180 top
C419  -  [C_0402]  167.51 100.81 180 top
C420  -  [C_0603]  167.63 108.56 90 top
C422  -  [C_0402]  205.35 27.05 90 top
C425  -  [C_0402]  202.08 35.83 0 top
C426  -  [C_0402]  202.3 40.36 180 top
C427  -  [C_0402]  203.95 38.16 270 top
C428  -  [C_0402]  201.9 28.74 90 top
C429  -  [C_0402]  202.96 28.63 90 top
C430  -  [C_0402]  50.65 72.55 0 top
C431  -  [C_0603]  60.76 70.27 90 bottom
C432  -  [C_0402]  198.93 73.43 270 bottom
C433  -  [C_0402]  198.76 75.03 180 bottom
C440  -  [C_0402]  273.43 50.47 270 top
C441  -  [C_0402]  273.41 52.63 270 top
C442  -  [C_0402]  278.99 49.76 0 bottom
C443  -  [C_0402]  275.98 48.92 0 bottom
C444  -  [C_B2]  267.5 82.79 0 bottom
C445  -  [C_0402]  268.5 72.06 90 top
C446  -  [C_0603]  230.43 83.27 180 bottom
C447  -  [C_0402]  230.48 84.3 180 bottom
C448  -  [C_0402]  263.29 85.52 135 top
C449  -  [C_0402]  262.66 84.89 135 top
C451  -  [C_0402]  163.96 88.02 0 top
C452  -  [C_0603]  158.98 18.43 270 top
C453  -  [C_0603]  181.84 73.01 180 top
C454  -  [C_0603]  96.06 56.55 270 top
C455  -  [C_0402]  31.59 7.86 0 top
C456  -  [C_0402]  10.48 21.08 0 top
C457  -  [C_0402]  15.03 6.6 270 top
C458  -  [C_0603]  133.07 76.71 270 top
C459  -  [C_0603]  134.38 76.72 270 top
C460  -  [C_0603]  128.42 70.57 270 top
C461  -  [C_0603]  137.39 67.65 0 top
CC1  -  [C_0402]  155.28 57.43 90 bottom
CC2  -  [C_0402]  155.28 56.57 270 bottom
CC3  -  [C_0402]  57.71 56.44 270 bottom
CC4  -  [C_0402]  56.81 60.2 270 bottom
CC5  -  [C_0402]  157.14 50.46 0 top
CC6  -  [C_0402]  137.9 88.87 0 bottom
CC7  -  [C_0402]  136.12 87.92 0 bottom
CC8  -  [C_0402]  168.14 74.7 90 top
CC9  -  [C_0402]  170.23 58.08 180 top
CC10  -  [C_0402]  58.61 60.17 180 top
CC11  -  [C_0402]  69.63 59.66 0 top
CC12  -  [C_0402]  124.59 56.87 180 top
CC13  -  [C_0402]  129.01 56.74 0 top
CC14  -  [C_0402]  147.83 52.04 180 top
CC15  -  [C_0402]  140.83 56.82 270 top
CC16  -  [C_0603]  128.77 55.66 0 top
CC17  -  [C_0603]  122.87 54.94 180 top
CC18  -  [C_0603]  128.77 54.39 0 top
CC19  -  [C_0603]  126.86 56.04 180 top
CC20  -  [C_0603]  126.86 54.77 180 top
CC21  -  [C_0603]  122.35 56.17 180 top
CC22  -  [C_0402]  109.98 93.65 270 top
CC24  -  [C_0402]  111.81 96.86 90 top
CC26  -  [C_0402]  136.65 69.62 180 top
CC27  -  [C_0402]  148.67 87.71 0 top
CC28  -  [C_0603]  141.47 69.82 90 top
CC29  -  [C_0402]  148.67 86.82 0 top
CC30  -  [C_0402]  165.03 61.61 270 bottom
CC31  -  [C_0402]  138.35 74.26 90 top
CC32  -  [C_0402]  145.8 68.43 180 top
CC33  -  [C_0402]  141.02 67.53 90 top
CC34  -  [C_0603]  137.2 90.14 0 top
CC35  -  [C_0402]  143.69 67.65 90 top
CC36  -  [C_0402]  154.69 68.99 0 top
CC37  -  [C_0402]  138.51 68.71 90 top
CC38  -  [C_0402]  142.77 68.43 180 top
CC39  -  [C_0402]  143.76 66.29 180 top
CC40  -  [C_0402]  144.78 73.13 180 top
CC41  -  [C_0402]  74.47 74.55 270 top
CC42  -  [C_0603]  140.77 87.53 90 bottom
CC43  -  [C_0603]  142.61 72.62 180 top
CC44  -  [C_0402]  139.88 69.43 90 top
CC45  -  [C_0402]  141.15 74.6 270 top
CC46  -  [C_0402]  142.55 69.87 90 top
CC47  -  [C_0805]  156.73 94.14 180 bottom
CC48  -  [C_0402]  69.63 62.33 0 top
CC49  -  [C_0603]  144.26 90.41 180 top
CC50  -  [C_0603]  135.14 90.13 180 top
CC51  -  [C_0402]  141.86 77 180 top
CC52  -  [C_0402]  129.46 67.65 90 top
CC53  -  [C_0402]  144.78 72.17 180 top
CC54  -  [C_0402]  144.34 70.84 180 top
CC55  -  [C_1206]  151.73 89.76 0 bottom
CC56  -  [C_0402]  139.88 72.12 270 top
CC58  -  [C_0402]  139.66 87.91 90 bottom
CC59  -  [C_0402]  141.16 75.48 180 top
CC60  -  [C_0402]  145.78 75.74 270 top
CC61  -  [C_0402]  142.61 87.97 90 top
CC62  -  [C_0603]  139.24 91.29 90 top
CC63  -  [C_0402]  142.57 74.98 270 top
CC64  -  [C_0402]  143.46 74.98 270 top
CC65  -  [C_0402]  139.37 55.04 270 top
CC66  -  [C_0402]  143.61 77.18 180 top
CC67  -  [C_0402]  114.05 16.48 180 top
CC68  -  [C_0402]  58.61 61.94 180 top
CC69  -  [C_0402]  135.82 29.35 270 top
CC70  -  [C_0402]  54.29 27.47 180 top
CC71  -  [C_D2]  188.73 72.75 180 bottom
CC72  -  [C_D2]  187.85 77.51 180 bottom
CC73  -  [C_D2]  157.76 90.78 0 bottom
CC74  -  [C_0402]  145.42 76.87 180 top
CC75  -  [C_1206]  161.4 94.27 0 bottom
CC76  -  [C_0603]  133.67 90.11 90 bottom
CC77  -  [C_0603]  135.78 91.53 270 bottom
CC78  -  [C_1206]  128.78 92.43 135 bottom
CC79  -  [C_1206]  141.59 91.2 90 bottom
CC81  -  [C_0402]  131.78 68.73 0 top
CC82  -  [C_0402]  70.68 69.76 180 top
CC90  -  [C_0402]  111.34 89.41 180 top
CC91  -  [C_0402]  109.41 90.31 90 top
CC149  -  [C_0402]  105.56 90.77 90 top
CC450  -  [C_0402]  152.73 88.06 0 bottom
CD1  -  [C_0402]  58.6 28.27 180 top
CD2  -  [C_0402]  58.61 29.18 180 top
CD3  -  [C_0402]  75.49 17.74 90 top
CD4  -  [C_0402]  84.06 26.78 270 top
CD5  -  [C_0402]  98.98 26.53 270 top
CD6  -  [C_0402]  98.49 17.25 180 top
CD7  -  [C_0402]  95.24 26.78 270 top
CD8  -  [C_0402]  82.03 17.87 90 top
CD9  -  [C_0402]  85.08 17.87 90 top
CD10  -  [C_0402]  87.81 26.21 270 top
CD11  -  [C_0402]  93.46 17.8 90 top
CD12  -  [C_0402]  114.91 18.39 0 top
CD13  -  [C_0402]  114.91 17.44 0 top
CD14  -  [C_0603]  83.24 17.63 90 top
CD15  -  [C_0603]  89.14 17.25 90 top
CD16  -  [C_0603]  85.71 26.71 270 top
CD17  -  [C_0603]  90.03 26.96 270 top
CD18  -  [C_0603]  92.25 27.03 270 top
CD19  -  [C_0603]  96.32 17.25 90 top
CD20  -  [C_0603]  90.54 17.18 90 top
CD21  -  [C_0603]  96.95 26.77 270 top
CD22  -  [C_D3]  100.25 46.37 90 top
CD23  -  [C_0402]  124.49 24.14 90 top
CD24  -  [C_0402]  121.6 25.31 180 top
CD25  -  [C_0402]  121.6 26.2 180 top
CD26  -  [C_0402]  122.53 25.31 0 top
CD27  -  [C_0402]  122.52 26.23 0 top
CD28  -  [C_0402]  122.78 17.78 0 top
CD29  -  [C_0402]  122.78 16.89 0 top
CD30  -  [C_0603]  122.81 18.88 0 top
CD31  -  [C_0603]  122.73 21.31 180 top
CD32  -  [C_0402]  133.09 25.73 270 top
CD33  -  [C_0402]  133.98 25.73 270 top
CD34  -  [C_0402]  74.6 17.74 90 top
CD35  -  [C_0402]  166.99 18.28 270 top
CD36  -  [C_0402]  169.6 18.21 270 top
CD37  -  [C_0402]  170.49 26.09 270 top
CD38  -  [C_0402]  173.6 26.09 270 top
CD39  -  [C_0402]  162.99 18.4 270 top
CD40  -  [C_0402]  165.66 26.28 270 top
CD41  -  [C_0402]  174.75 26.39 270 top
CD42  -  [C_0402]  160.66 18.43 270 top
CD43  -  [C_0402]  171.76 18.27 270 top
CD44  -  [C_0402]  170.87 18.27 270 top
CD45  -  [C_0603]  165.53 18.77 270 top
CD46  -  [C_0603]  164.14 18.96 270 top
CD47  -  [C_0603]  161.91 18.96 270 top
CD48  -  [C_0603]  168.52 26.77 270 top
CD49  -  [C_0603]  172 26.64 270 top
CD50  -  [C_0603]  168.33 18.71 270 top
CD51  -  [C_0603]  175.95 26.71 270 top
CD52  -  [C_0603]  166.74 26.45 270 top
CD53  -  [C_D3]  156.2 37.91 270 top
CD54  -  [C_0402]  199.36 25.57 0 top
CD55  -  [C_0402]  199.36 26.58 0 top
CD56  -  [C_0402]  199.23 17.31 0 top
CD57  -  [C_0402]  199.23 18.2 0 top
CD58  -  [C_0603]  199.19 19.34 0 top
CD59  -  [C_0603]  199.25 23.02 180 top
CD60  -  [C_0402]  199.36 28.36 0 top
CD61  -  [C_0402]  199.36 27.47 0 top
CE1  -  [C_0402]  74.38 72.05 90 bottom
CE2  -  [C_0402]  74.38 74.7 270 bottom
CE7  -  [C_0805]  110.21 96.89 270 bottom
CE8  -  [C_0402]  133.58 96.23 90 bottom
CE9  -  [C_0402]  131.31 96.23 90 bottom
CMOS1  -  [SHORTPADS]  54.74 51.36 270 bottom
D1  -  [RB751V40_SC76-2]  52.63 45.08 270 top
D2  -  [BAT54CW_SOT323-3]  56.02 69.06 90 top
D8  -  [L30ESDL5V0C3-2_SOT23-3]  78.61 74.13 270 bottom
D10  -  [BAT54CW_SOT323-3]  60.56 74.99 90 top
D12  -  [RB751S40T1G_SOD523-2]  210.53 17.98 90 top
D13  -  [RB751S40T1G_SOD523-2]  211.05 23.3 90 top
D14  -  [RB751S40T1G_SOD523-2]  210.54 28.22 90 top
D15  -  [TVWDF1004AD0_DFN9]  209.5 95.91 270 top
D16  -  [L30ESDL5V0C3-2_SOT23-3]  210.13 93.83 270 bottom
D17  -  [TVWDF1004AD0_DFN9]  76.46 92.13 0 top
D18  -  [L30ESDL5V0C3-2_SOT23-3]  73.97 94.49 180 top
D19  -  [RB751S40T1G_SOD523-2]  150.2 109.02 180 top
D20  -  [PESD24VS2UT_SOT23-3]  105.93 95.72 90 bottom
D21  -  [BAT54CW_SOT323-3]  57.81 83.83 270 top
D23  -  [RB751S40T1G_SOD523-2]  193.59 93.88 180 top
D24  -  [RB751S40T1G_SOD523-2]  190.08 93.9 0 top
D30  -  [L03ESDL5V0CC3-2_SOT23-3]  277.27 51.21 90 top
D31  -  [L03ESDL5V0CC3-2_SOT23-3]  273.1 50.56 180 bottom
D32  -  [L03ESDL5V0CC3-2_SOT23-3]  277.48 50.62 180 bottom
D33  -  [L30ESDL5V0C3-2_SOT23-3]  267.64 79.12 270 bottom
D34  -  [TVWDF1004AD0_DFN9]  267.9 81.65 225 top
D65  -  [RB751VM-40TE-17_SOD323-2]  199.95 98.43 270 bottom
FD1  -  [FIDUCIAL_C40M80]  239.38 100.25 180 bottom
FD2  -  [FIDUCIAL_C40M80]  12.27 9.28 180 bottom
FD3  -  [FIDUCIAL_C40M80]  70.18 92.89 0 top
FD4  -  [FIDUCIAL_C40M80]  277.33 7.06 0 top
H1  -  [H_2P8]  50.48 85.15 0 top
H2  -  [H_2P8]  184.6 13.92 0 top
H3  -  [H_2P8]  280.2 2.15 0 top
H4  -  [H_2P8]  80.2 5.05 0 top
H5  -  [H_2P3]  227.2 110.55 0 top
H8  -  [H_3P4]  158.32 83.87 0 top
H9  -  [H_3P4]  103 61.73 0 top
H10  -  [H_3P4]  103 83.87 0 top
H11  -  [H_3P4]  158.32 61.73 0 top
H12  -  [H_2P8]  280.2 45.15 0 top
H13  -  [H_2P8]  215.87 75.35 0 top
H14  -  [H_2P1]  49.2 81 0 top
H15  -  [H_2P8]  44.7 42.53 0 top
H16  -  [H_2P8]  146.65 4.94 0 top
H17  -  [H_2P8]  267.2 92.15 0 top
H18  -  [H_2P8]  207.95 34.05 0 top
JAPS1  -  [ACES_50506-01841-P01_18P]  40.24 46.73 210 top
JDEG1  -  [ACES_50521-01041-P01_10P-T]  8.67 42.73 180 bottom
JDIMM1  -  [FOX_AS0A621-U4R6-7H_204P]  59.5 25.95 180 bottom
JDIMM2  -  [FOX_AS0A621-U4R6-7H_204P]  136 25.95 180 bottom
JDOCK1  -  [JAE_WD2F144WB8-DT_144P-T]  113.45 100.55 0 bottom
JEDP1  -  [ACES_50398-04071-001_40P]  52.57 70.8 200 bottom
JFAN1  -  [ACES_50277-0040N-001_4P-T]  52.59 56.72 238 top
JHDMI1  -  [LCN_AUF05-1922S10-0019_19P-T]  190.65 104.17 0 bottom
JHP1  -  [SINGA_2SJ3080-003111F_6P-T]  272.31 64.98 90 bottom
JKBTP1  -  [E-T_6718K-Y16N-01L_16P-T]  197.45 5.9 0 top
JLED1  -  [ACES_50450-0067N-P01_6P-T]  123.45 98.84 90 top
JLOM1  -  [SANTA_130456-341_13P-T]  249.38 100.78 0 bottom
JMDP1  -  [ACON_MAR2C-20K1800_20P-T]  274.79 93.35 90 bottom
JMEDIA  -  [E-T_6718K-Y06N-01L_6P-T]  65.85 81.65 180 top
JMINI1  -  [LCN_DAN08-52216-0100_52P-T]  211.45 8.8 270 bottom
JMINI2  -  [LCN_DAN08-52216-0100_52P-T]  207.25 40.55 270 bottom
JMINI3  -  [LCN_DAN08-52406-0500_52P]  48.2 31.85 270 bottom
JNFC1  -  [E-T_6718K-Y15N-01L_15P-T]  247.96 5.1 0 top
JRTC1  -  [TYCO_2-1775293-2_2P]  275.88 36.46 180 bottom
JSD1  -  [ALPS_SCDADA0101_19P_NR-T]  249.58 23.9 270 bottom
JSF1  -  [ACES_50277-0040N-001_4P-T]  7.11 16.96 270 top
JSH1  -  [E-T_6718K-Y12N-01L_12P-T]  262.53 5.9 0 top
JSPK1  -  [ACES_50209-0040N-001_4P]  282.48 12.67 270 top
JTAA1  -  [ACES_50185-02041-001_20P-T]  173.63 79.47 180 bottom
JTAG1  -  [SHORTPADS]  11.48 15.4 180 top
JUSB1  -  [SANTA_373070-1_9P-T]  75.2 98.14 0 bottom
JUSB2  -  [SANTA_373070-1_9P-T]  218.1 98.14 0 bottom
JUSB3  -  [TAITW_PUBAUE-09FLBS1FF4H0_9P-T]  271.47 72.25 270 bottom
JUSH1  -  [E-T_6718K-Y20N-00L_20P-T]  183.26 5.9 0 top
JXDP1  -  [SAMTE_BSH-030-01-L-D-A_60P]  66.83 49.63 90 top
L1  -  [MURAT_BLM18AG102SN1D_2P]  202.73 76.61 180 bottom
L2  -  [MURAT_BLM18AG102SN1D_2P]  198.78 86.08 0 bottom
L4  -  [MURAT_BLM18AG102SN1D_2P]  202.56 74.41 0 bottom
L5  -  [MURAT_BLM18AG102SN1D_2P]  187.06 89.38 0 top
L8  -  [MURAT_DLW21HN900SQ2L_4P]  68.45 70.59 110 bottom
L9  -  [DELTA_0402HS-9N0EJTS_2P]  193.73 96.71 90 bottom
L10  -  [MURAT_DLW21SN900HQ2L-0805_4P-S]  193.94 96.34 90 bottom
L11  -  [DELTA_0402HS-9N0EJTS_2P]  195 96.71 90 bottom
L12  -  [DELTA_0402HS-9N0EJTS_2P]  196.14 96.71 90 bottom
L13  -  [MURAT_DLW21SN900HQ2L-0805_4P-S]  196.35 96.34 90 bottom
L14  -  [DELTA_0402HS-9N0EJTS_2P]  197.41 96.71 90 bottom
L15  -  [DELTA_0402HS-9N0EJTS_2P]  191.31 96.71 90 bottom
L16  -  [MURAT_DLW21SN900HQ2L-0805_4P-S]  191.52 96.34 90 bottom
L17  -  [DELTA_0402HS-9N0EJTS_2P]  192.58 96.71 90 bottom
L18  -  [DELTA_0402HS-9N0EJTS_2P]  188.96 96.71 90 bottom
L19  -  [MURAT_DLW21SN900HQ2L-0805_4P-S]  189.17 96.34 90 bottom
L20  -  [DELTA_0402HS-9N0EJTS_2P]  190.23 96.71 90 bottom
L21  -  [CHILI_PBY160808T-600Y-N_2P]  270.54 24.19 270 top
L22  -  [MURAT_BLM18PG330SN1D_2P]  280.23 20.53 270 top
L23  -  [MURAT_BLM18PG330SN1D_2P]  277.61 20.51 270 top
L24  -  [MURAT_BLM18PG330SN1D_2P]  275.36 20.5 270 top
L25  -  [MURAT_BLM18PG330SN1D_2P]  273.27 20.54 270 top
L26  -  [TAIYO_CBC2012T4R7M_2P]  260.27 72.23 270 top
L27  -  [DELTA_0603CS-120EJTS_2P]  232.05 103.91 180 bottom
L28  -  [DELTA_0603CS-120EJTS_2P]  232.05 102.39 180 bottom
L29  -  [DELTA_0603CS-120EJTS_2P]  233.51 100.86 180 bottom
L30  -  [DELTA_0603CS-120EJTS_2P]  233.51 99.34 180 bottom
L31  -  [DELTA_0603CS-120EJTS_2P]  233.51 97.81 180 bottom
L32  -  [DELTA_0603CS-120EJTS_2P]  233.51 96.29 180 bottom
L33  -  [DELTA_0603CS-120EJTS_2P]  233.51 94.77 180 bottom
L34  -  [DELTA_0603CS-120EJTS_2P]  233.51 93.24 180 bottom
L35  -  [MURAT_BLM15AG601SN1D_2P]  252.45 10.83 0 top
L36  -  [MURAT_BLM15AG601SN1D_2P]  264.8 24.74 180 top
L37  -  [MURAT_DLW21SN670HQ2L_4P]  204.59 94.56 0 top
L38  -  [MURAT_DLW21SN670HQ2L_4P]  204.66 92.46 0 top
L39  -  [MURAT_DLW21HN900SQ2L_4P]  202.27 90.51 0 bottom
L40  -  [MURAT_DLW21SN900HQ2L-0805_4P]  76.93 88.79 90 top
L41  -  [MURAT_DLW21SN900HQ2L-0805_4P]  78.99 88.71 90 top
L42  -  [CHENG_OCE2012120YZF_4P]  74.31 88.74 90 top
L43  -  [MURAT_DLW21SN900SQ2L-0805_4P-S]  124.19 95.7 0 top
L46  -  [MURAT_DLW21SN900SQ2L-0805_4P-S]  268.12 13.43 270 top
L47  -  [MURAT_DLW21SN900SQ2L-0805_4P-S]  260.86 10.68 0 top
L48  -  [MURAT_DLW21SN900SQ2L-0805_4P-S]  260.86 8.58 0 top
L51  -  [MURAT_BLM18AG221SN1D_2P]  275.57 45.73 180 bottom
L52  -  [MURAT_BLM18AG221SN1D_2P]  272.37 52.16 180 top
L54  -  [MURAT_DLW21HN900SQ2L_4P]  265.01 76.31 90 top
L55  -  [MURAT_DLW21SN900HQ2L-0805_4P]  265.07 85.47 315 top
L56  -  [MURAT_DLW21SN900HQ2L-0805_4P]  263.59 83.99 315 top
LC1  -  [MURAT_LQM2MPN2R2NG0L_2P]  142.99 93.2 270 top
LC2  -  [MURAT_LQM2MPN2R2NG0L_2P]  145.21 93.2 270 top
LC3  -  [MURAT_LQM2MPN2R2NG0L_2P]  143.69 90.68 90 bottom
LC4  -  [MURAT_LQM2MPN2R2NG0L_2P]  158.45 94.27 0 bottom
LC5  -  [MURAT_LQM2MPN2R2NG0L_2P]  153.19 88.86 180 top
LC6  -  [MURAT_LQM2MPN2R2NG0L_2P]  130.59 88.11 0 bottom
LE1  -  [MURAT_BLM15BB221SN1D_2P]  60.88 79.44 180 top
LED1  -  [LED_LTW-193ZDS5_2P]  227.65 101.27 180 top
LED5  -  [LED_LTW-193ZDS5_2P]  203.9 101.45 0 top
LED6  -  [LED_LTW-193ZDS5_2P]  186.4 101.45 180 top
LED7  -  [LED_LTW-295DSKS-5A_4P]  194.55 101.1 0 top
ME1  -  [SHORTPADS]  55.22 53.21 0 bottom
NOREF  -  []  267.2 92.15 0 top
NOREF#2  -  []  280.2 2.15 0 top
NOREF#3  -  []  71.88 210.97 0 top
NOREF#4  -  []  50.48 85.15 0 top
NOREF#5  -  []  184.6 13.92 0 top
NOREF#6  -  []  44.7 42.53 0 top
NOREF#7  -  []  184.6 13.91 0 top
NOREF#8  -  []  84.81 48 0 top
NOREF#9  -  []  146.65 4.94 0 top
NOREF#10  -  []  120.32 46.2 0 top
NOREF#11  -  []  162.2 45.44 0 top
NOREF#12  -  []  146.65 4.94 0 top
NOREF#13  -  []  207.95 34.05 0 top
NOREF#14  -  []  1.6 2.7 0 top
NOREF#15  -  []  103 83.87 0 top
NOREF#16  -  []  49.2 81 0 top
NOREF#17  -  []  80.2 5.05 0 top
NOREF#18  -  []  80.2 5.05 0 top
NOREF#19  -  []  280.2 45.15 0 top
NOREF#20  -  []  79.49 41.97 0 top
NOREF#21  -  []  184.6 13.91 0 top
NOREF#22  -  []  215.87 75.35 0 top
NOREF#23  -  []  158.32 83.87 0 top
NOREF#24  -  []  158.32 61.73 0 top
NOREF#25  -  [unnamed#2]  153.42 66 0 top
NOREF#26  -  []  108.76 -72.54 0 top
NOREF#27  -  []  103 61.73 0 top
NOREF#28  -  []  65.27 17.94 0 top
NOREF#29  -  []  44.7 42.53 0 top
NOREF#30  -  []  267.2 92.15 0 top
NOREF#31  -  []  101.2 109.65 0 top
NOREF#32  -  []  215.87 75.35 0 top
NOREF#33  -  []  227.2 110.55 0 top
NOREF#34  -  []  280.2 45.15 0 top
NOREF#35  -  []  184.6 13.92 0 top
NOREF#36  -  []  127.43 46.52 180 bottom
NOREF#37  -  []  163.72 43.25 180 bottom
NOREF#38  -  []  141.78 34.45 180 bottom
PBATT1  -  [ALLTO_C144LS-109A9-L_9P-T]  170.2 2.3 180 bottom
PC1  -  [C_0603]  266.12 67.22 90 top
PC2  -  [C_0603]  172.39 6.96 0 top
PC3  -  [C_0402]  172.38 5.88 0 top
PC4  -  [C_0402]  154.61 11.61 270 top
PC5  -  [C_0805]  51.92 39.01 180 top
PC6  -  [C_0603]  54.45 30.37 0 top
PC7  -  [C_0603]  54.45 31.66 0 top
PC8  -  [C_0603]  54.45 32.93 0 top
PC9  -  [C_0603]  81.62 81.88 270 top
PC10  -  [C_0805]  54.5 34.45 0 top
PC11  -  [C_0603]  50.1 37.15 270 top
PC12  -  [C_0603]  91.49 81.89 270 bottom
PC100  -  [C_0603]  197.73 43.66 90 top
PC101  -  [C_0402]  195.99 55.46 90 top
PC102  -  [C_0805]  197.29 54.94 90 top
PC103  -  [C_0805]  199.01 55.36 90 top
PC104  -  [C_0805]  193.7 55.19 90 top
PC105  -  [C_0402]  195.1 55.46 90 top
PC106  -  [C_0402]  185.46 54.46 180 top
PC107  -  [C_0805]  191.92 55.19 90 top
PC108  -  [C_0402]  185.46 55.41 180 top
PC109  -  [C_0603]  200.65 48.93 0 top
PC110  -  [C_0603]  191.57 49.06 0 top
PC111  -  [C_0603]  202.37 60.93 90 top
PC112  -  [C_0603]  195.71 64.91 180 bottom
PC113  -  [C_V]  197.98 67.86 0 bottom
PC114  -  [C_0603]  189.28 61.1 90 top
PC115  -  [C_V]  185.42 64.26 180 bottom
PC116  -  [C_0603]  184.81 61.28 270 top
PC117  -  [C_0603]  197.99 53.16 0 top
PC118  -  [C_0603]  196.2 53.31 180 top
PC119  -  [C_0603]  192.94 46 180 top
PC200  -  [C_0805]  109.78 12.08 90 top
PC201  -  [C_0805]  108 12.08 90 top
PC202  -  [C_0402]  106.73 7.05 270 bottom
PC203  -  [C_0402]  107.62 7.05 270 bottom
PC204  -  [C_0603]  112.7 12.89 180 top
PC205  -  [C_0805]  116.41 6.49 270 top
PC207  -  [C_D2]  96.38 13.17 270 bottom
PC208  -  [C_0603]  101.97 12.42 90 top
PC209  -  [C_0603]  120.37 14.17 180 top
PC211  -  [C_0603]  118.97 15.38 0 top
PC212  -  [C_0402]  117.78 6.65 270 top
PC213  -  [C_0402]  120.41 5.47 180 top
PC214  -  [C_0402]  121.26 6.32 0 top
PC215  -  [C_0402]  119.52 9.07 0 top
PC300  -  [C_0402]  230.99 71.54 0 bottom
PC301  -  [C_0402]  230.99 70.65 0 bottom
PC302  -  [C_0805]  230.53 73.38 0 top
PC303  -  [C_0805]  230.53 71.6 0 top
PC304  -  [C_0603]  233.41 70.9 90 top
PC305  -  [C_0402]  234.43 75.62 270 top
PC306  -  [C_0603]  229.16 79.07 0 top
PC307  -  [C_B2]  226.77 79.79 180 bottom
PC308  -  [C_0402]  239.94 74.33 0 top
PC400  -  [C_0402]  102.69 94.5 270 bottom
PC401  -  [C_0805]  99.42 97.69 180 bottom
PC402  -  [C_0402]  102.68 91.85 90 bottom
PC403  -  [C_0402]  93.48 93.85 270 bottom
PC404  -  [C_0805]  94.22 95.2 180 bottom
PC500  -  [C_0603]  91.31 72.55 270 bottom
PC501  -  [C_0402]  90.61 69.7 180 top
PC502  -  [C_0402]  94.25 70.55 180 top
PC503  -  [C_0402]  78.27 65.7 0 bottom
PC504  -  [C_0402]  78.42 67.8 0 bottom
PC505  -  [C_0603]  88.96 74.78 180 bottom
PC506  -  [C_0402]  93.1 77.57 180 top
PC507  -  [C_0603]  91.31 74.52 90 bottom
PC508  -  [C_0603]  83.99 60.49 90 bottom
PC509  -  [C_0603]  86.97 67.28 180 bottom
PC510  -  [C_0603]  89.6 75.98 90 bottom
PC511  -  [C_0402]  85.4 78.65 270 top
PC512  -  [C_0402]  92.25 80.38 270 top
PC513  -  [C_0402]  94.25 69.66 180 top
PC514  -  [C_0402]  88.3 80.59 0 top
PC700  -  [C_0603]  46.09 3.63 180 top
PC703  -  [C_0603]  51.49 7.21 180 bottom
PC704  -  [C_0603]  48.43 7.43 90 top
PC705  -  [C_0603]  50.09 8.48 0 bottom
PC706  -  [C_0805]  51.13 11.47 180 top
PC707  -  [C_0402]  56.05 15.46 90 top
PC708  -  [C_0402]  50.56 4.84 270 top
PC709  -  [C_0603]  55.31 11.43 90 top
PC711  -  [C_0805]  58.92 12.79 270 top
PC712  -  [C_0805]  57.2 12.79 270 top
PC713  -  [C_0603]  52.31 13.56 270 top
PC714  -  [C_0603]  63.93 3.78 180 top
PC715  -  [C_0603]  81.84 11.47 180 top
PC716  -  [C_0805]  72.92 7.24 270 top
PC717  -  [C_0805]  81.99 14.72 180 top
PC718  -  [C_0805]  81.99 12.99 180 top
PC719  -  [C_0402]  52.31 3.82 90 top
PC720  -  [C_0603]  53.7 7.64 0 bottom
PC721  -  [C_0603]  58.69 5.92 180 top
PC722  -  [C_0603]  55.16 6.44 180 bottom
PC724  -  [C_0402]  94.17 82.84 90 top
PC725  -  [C_0402]  93.28 82.84 90 top
PC726  -  [C_0402]  94.3 86.61 270 top
PC727  -  [C_0402]  96.56 86.52 0 top
PC728  -  [C_0402]  98.86 87.78 90 top
PC729  -  [C_0402]  96.81 82.82 90 top
PC730  -  [C_0402]  96.9 81.51 270 bottom
PC731  -  [C_0805]  80.6 62.41 0 top
PC732  -  [C_0805]  80.6 60.69 0 top
PC733  -  [C_0603]  46.48 5.37 90 top
PC734  -  [C_0805]  80.58 62.38 0 bottom
PC735  -  [C_D]  80.77 57.39 0 bottom
PC736  -  [C_0805]  80.58 60.67 0 bottom
PC737  -  [C_0805]  74.65 7.24 270 top
PC738  -  [C_D]  77.75 62.74 180 bottom
PC740  -  [C_0402]  92.37 84.7 0 top
PC741  -  [C_0805]  57.33 14.67 90 top
PC742  -  [C_0805]  59.04 14.67 90 top
PC801  -  [C_0402]  131.12 7.91 0 top
PC803  -  [C_0603]  204.5 7.47 0 bottom
PC805  -  [C_0402]  127.76 12.36 180 top
PC806  -  [C_0402]  203.87 6.34 0 bottom
PC807  -  [C_0805]  201.69 7.28 180 bottom
PC808  -  [C_0402]  144.01 10.27 270 top
PC809  -  [C_0402]  192.18 11.39 0 top
PC810  -  [C_0402]  137.31 9.25 180 top
PC811  -  [C_0603]  156.77 12.36 270 bottom
PC812  -  [C_0402]  132.63 5.12 270 top
PC813  -  [C_0603]  4.12 23.02 270 top
PC814  -  [C_0402]  211.43 2.82 180 top
PC815  -  [C_0603]  5.32 23.02 270 top
PC816  -  [C_0603]  11.67 26.07 270 top
PC817  -  [C_0402]  11.85 27.03 0 top
PC900  -  [C_0805]  99.17 66.41 90 bottom
PC901  -  [C_0805]  93.97 76.4 90 bottom
PC902  -  [C_0805]  93.9 66.75 90 bottom
PC903  -  [C_0805]  95.66 66.79 90 bottom
PC904  -  [C_0805]  106.1 69.71 90 bottom
PC905  -  [C_0805]  106.08 73.06 90 bottom
PC906  -  [C_0805]  106.11 66.41 90 bottom
PC907  -  [C_0805]  95.69 73.09 90 bottom
PC908  -  [C_0805]  97.45 66.41 90 bottom
PC909  -  [C_0805]  106.08 76.44 90 bottom
PC910  -  [C_0805]  95.69 69.74 90 bottom
PC911  -  [C_0805]  95.72 76.42 90 bottom
PC912  -  [C_0805]  100.9 66.41 90 bottom
PC913  -  [C_0805]  100.88 69.72 90 bottom
PC914  -  [C_0805]  99.15 69.72 90 bottom
PC915  -  [C_0805]  97.42 69.72 90 bottom
PC916  -  [C_0805]  102.62 76.43 90 bottom
PC917  -  [C_0805]  100.88 73.08 90 bottom
PC918  -  [C_0805]  99.15 73.08 90 bottom
PC919  -  [C_0805]  97.42 73.08 90 bottom
PC920  -  [C_0805]  104.34 76.43 90 bottom
PC921  -  [C_0805]  100.89 76.42 90 bottom
PC922  -  [C_0805]  102.64 66.41 90 bottom
PC923  -  [C_0805]  99.17 76.42 90 bottom
PC924  -  [C_0805]  97.45 76.42 90 bottom
PC925  -  [C_0805]  104.34 73.06 90 bottom
PC926  -  [C_0805]  104.34 69.72 90 bottom
